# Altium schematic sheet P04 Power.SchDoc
size 246 x 182 mm
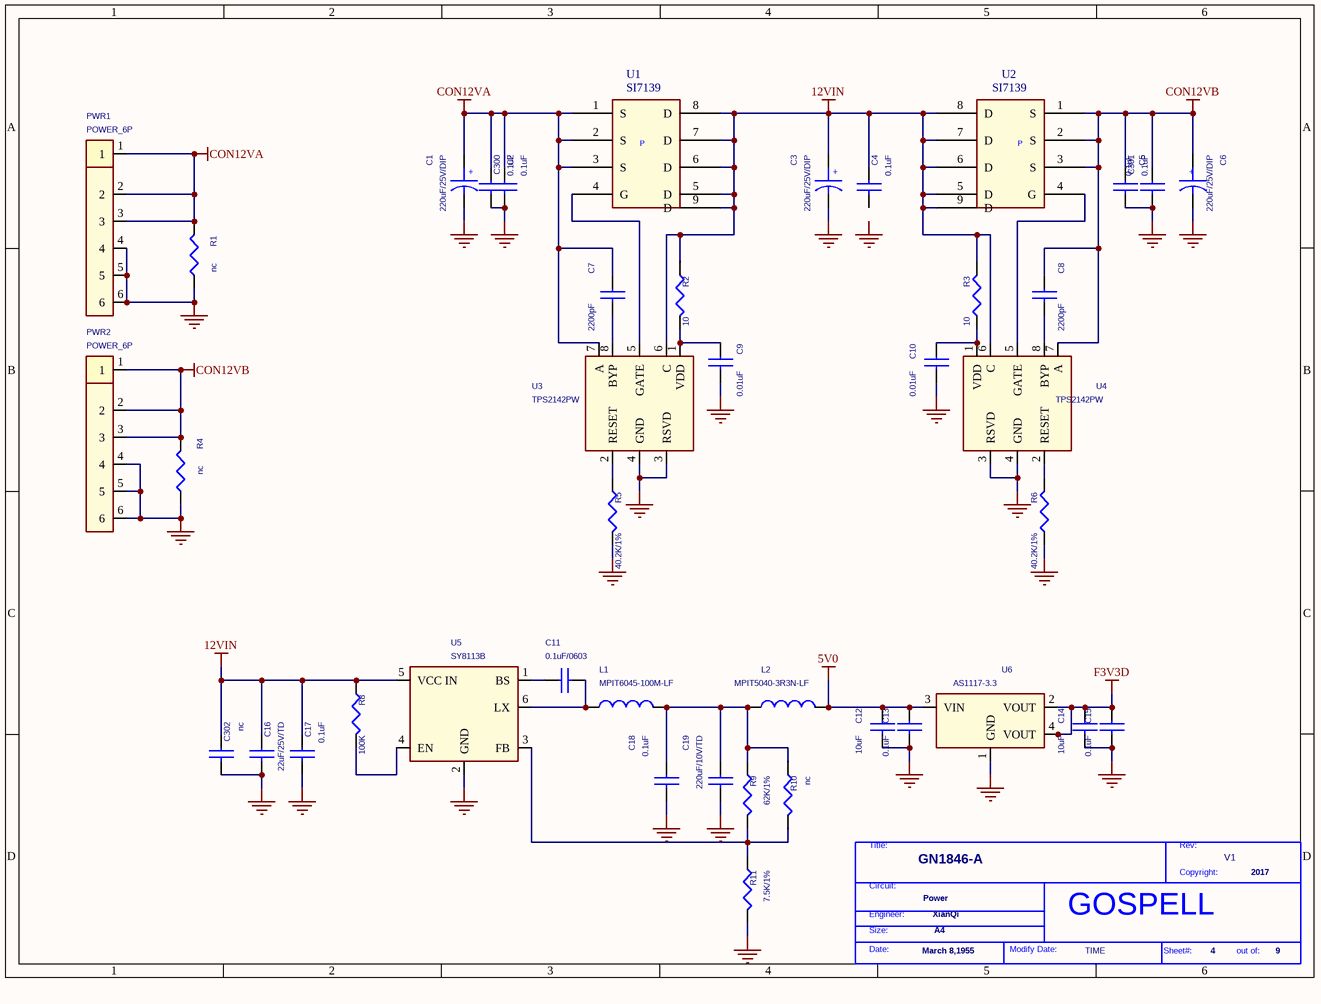
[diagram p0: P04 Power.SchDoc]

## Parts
*  Doc: Power  Page Count: 9  Page Number: 4  Page Create Date: March 8,1955  Page Size: A4  RevCode: V1  Title: GN1846-A  Copyright: 2017  Engineer: XianQi  Page Modify Date: TIME  (hidden comment: GOSPELL)  (graphical)
C1  220uF/25V/DIP  [CE8X3.5]
C2  0.1uF  [0402C]
C3  220uF/25V/DIP  [CE8X3.5]
C4  0.1uF  [0402C]
C5  0.1uF  [0402C]
C6  220uF/25V/DIP  [CE8X3.5]
C7  2200pF  [0402C]
C8  2200pF  [0402C]
C9  0.01uF  [0402C]
C10  0.01uF  [0402C]
C11  0.1uF/0603  [0402C]
C12  10uF  [C0603]
C13  0.1uF  [0402C]
C14  10uF  [C0603]
C15  0.1uF  [0402C]
C16  22uF/25V/TD  [C6032]
C17  0.1uF  [0402C]
C18  0.1uF  [0402C]
C19  220uF/10V/TD  [C6032]
C300  0.1uF  [C1206]
C301  0.1uF  [C1206]
C302  nc  [C1206]
L1  MPIT6045-100M-LF  [MPI6045]
L2  MPIT5040-3R3N-LF  [FB0805]
PWR1  POWER_6P  [TJC2-6]
PWR2  POWER_6P  [TJC2-6]
R1  nc  [0805]
R2  10  [R0603]
R3  10  [R0603]
R4  nc  [0805]
R5  40.2K/1%  [0402R]
R6  40.2K/1%  [0402R]
R8  100K  [0402R]
R9  62K/1%  [0402R]
R10  nc  [0402R]
R11  7.5K/1%  [0402R]
U1  SI7139  [PowerPAKSO8]
U2  SI7139  [PowerPAKSO8]
U3  TPS2142PW  [TSSOP-8]
U4  TPS2142PW  [TSSOP-8]
U5  SY8113B  [SOT23_6_G]
U6  AS1117-3.3  [SOT223]

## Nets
5V0: C12.1 C13.1 L2.2 U6.3(VIN)
12VIN: C3.1 C4.1 C16.1 C17.1 C302.1 R2.1 R3.1 R8.1 U1.5(D) U1.6(D) U1.7(D) U1.8(D) U1.9(D) U2.5(D) U2.6(D) U2.7(D) U2.8(D) U2.9(D) U3.6(C) U4.6(C) U5.5(VCC_IN)
CON12VA: C1.1 C2.1 C7.1 C300.1 PWR1.1 PWR1.2 PWR1.3 R1.1 U1.1(S) U1.2(S) U1.3(S) U3.7(A)
CON12VB: C5.1 C6.1 C8.1 C301.1 PWR2.1 PWR2.2 PWR2.3 R4.1 U2.1(S) U2.2(S) U2.3(S) U4.7(A)
F3V3D: C14.1 C15.1 U6.2(VOUT) U6.4(VOUT)
GND: C1.2 C2.2 C3.2 C5.2 C6.2 C9.2 C10.2 C12.2 C13.2 C14.2 C15.2 C16.2 C17.2 C18.2 C19.2 C300.2 C301.2 C302.2 PWR1.4 PWR1.5 PWR1.6 PWR2.4 PWR2.5 PWR2.6 R1.2 R4.2 R5.2 R6.2 R11.2 U3.3(RSVD) U3.4(GND) U4.3(RSVD) U4.4(GND) U5.2(GND) U6.1(GND)
NetC7_2: C7.2 U3.8(BYP)
NetC8_2: C8.2 U4.8(BYP)
NetC9_1: C9.1 R2.2 U3.1(VDD)
NetC10_1: C10.1 R3.2 U4.1(VDD)
NetC11_1: C11.1 U5.1(BS)
NetC11_2: C11.2 L1.1 U5.6(LX)
NetC18_1: C18.1 C19.1 L1.2 L2.1 R9.1 R10.1
NetR5_1: R5.1 U3.2(RESET)
NetR6_1: R6.1 U4.2(RESET)
NetR8_2: R8.2 U5.4(EN)
NetR9_2: R9.2 R10.2 R11.1 U5.3(FB)
NetU1_4: U1.4(G) U3.5(GATE)
NetU2_4: U2.4(G) U4.5(GATE)

Not connected (* = marked no-connect by the designer): C4 2

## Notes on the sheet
- Labels drawn without touching a wire or pin: GND

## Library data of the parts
C1 C3 C6 = CAP POL
C2 C4 C5 C7-C11 C16-C19 C300-C302 = CAP NP
C12-C15 = CAP NP_Dup1
L1 L2 = CHOKE TORROID_0
PWR1 PWR2 = POWER_4P
R1-R6 R8-R11 = R
U5 = SY8120
U6 = AS1117-X_0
